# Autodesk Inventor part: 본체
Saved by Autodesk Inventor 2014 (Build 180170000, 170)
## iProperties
Created: 2026-04
Part Number: 본체
Material: 알루미늄 6061
Document SubType Name: Modeling
Designer: dg
Density: 2.71 g/cm^3
Appearance: 알루미늄 - 평지
Mass: 5647.51 g
Surface Area: 3056.68 cm^2
Volume: 2083.95 cm^3
Author: jhkim
Creation Date: 2026-03-27
Sending System: Autodesk Inventor 2026
Preprocessor: ST-DEVELOPER v20.1
Author: dg
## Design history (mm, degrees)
node "본체1"
node "솔리드1"
node "기준1"
